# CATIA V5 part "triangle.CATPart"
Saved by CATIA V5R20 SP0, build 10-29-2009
Part number: triangle
Bounding box of the stored display mesh (mm): x 5 to 15, y 29.615 to 116.94, z 74.488 to 194.386
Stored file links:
  C:\Users\Willy\Documents\ThinkMotion\646\triangle.CATPart
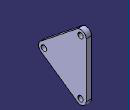
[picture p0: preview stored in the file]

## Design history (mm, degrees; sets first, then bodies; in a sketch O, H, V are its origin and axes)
Body1 (main body)
  DatumSurface1
  Sketch1 on face of DatumSurface1, origin (5, 0, 0), H (0, 1, 0), V (0, 0, 1)
    circle A1 centre (106.9401, 184.4161) radius 5
    point P1 (106.9401, 184.4161)
    circle A2 centre (106.9401, 84.4161) radius 5
    point P2 (106.9401, 84.4161)
    circle A3 centre (39.496, 131.0561) radius 5
    point P3 (39.496, 131.0561)
    axis line L1 (106.9401, 234.2997) -> (106.9401, 44.2997)
    arc A4 centre (106.9401, 84.4161) radius 10 from (101.2523, 76.1912) to (116.9401, 84.4161) ccw
    arc A5 centre (39.496, 131.0561) radius 10 from (33.2913, 138.8985) to (33.8082, 122.8312) ccw
    arc A6 centre (106.9401, 184.4161) radius 10 from (116.9401, 184.3935) to (100.7355, 192.2585) ccw
    line L2 (116.9401, 184.3935) -> (116.9401, 84.4161)
    line L3 (101.2523, 76.1912) -> (33.8082, 122.8312)
    line L4 (100.7355, 192.2585) -> (33.2913, 138.8985)
    distance P2 P1 = 100
    radius A1 = 5
    radius A2 = 5
    radius A3 = 5
    distance P1 P3 = 86
    distance P3 P2 = 82
    radius A4 = 10
    radius A5 = 10
    radius A6 = 10
    vertical: L1 V
    coincidence: P2 L1, P1 L1
    tangency: L2 A4, L3 A5, A4 L3, L4 A5, L4 A6
  Pad1: profile Sketch1, direction (1, 0, 0), length 10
